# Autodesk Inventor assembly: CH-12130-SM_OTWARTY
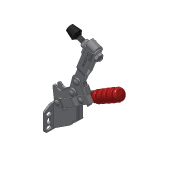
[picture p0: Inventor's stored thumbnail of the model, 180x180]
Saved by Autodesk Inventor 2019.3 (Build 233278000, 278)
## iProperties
Company: Î¢ÈíÖÐ¹ú
Created: 2012-09
Part Number: CH-12130-SM_OTWARTY
Material: Ogólny
Description: STEP AP203
Document SubType Name: Assembly
Designer: CADENGINEERING4
Sending System: SolidWorks 2010
Preprocessor: SwSTEP 2.0
Title: CH-12130-SM.STEP
Author: Î¢ÈíÓÃ»§
Revision Number: ÈÎºÎ
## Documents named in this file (12)
- D:\Vault_2016\Projekty\NASZ KATALOG\CLAMPTEK\STRONA\Vertical toggle clamp\CH-12130-SM\CH-12130-SM_OTWARTY.iam
- D:\Vault_2016\Projekty\NASZ KATALOG\CLAMPTEK\STEP FILES\Vertical toggle clamp\CH-12130-SM\CH-12130-04 CONNECTING-PLATE.ipt
- D:\Vault_2016\Projekty\NASZ KATALOG\CLAMPTEK\STEP FILES\Vertical toggle clamp\CH-12130-SM\CH-12130-SM-01 SIDE MOUNTED.ipt
- D:\Vault_2016\Projekty\NASZ KATALOG\CLAMPTEK\STEP FILES\Vertical toggle clamp\CH-12130-SM\CH-12130-08.ipt
- D:\Vault_2016\Projekty\NASZ KATALOG\CLAMPTEK\STEP FILES\Vertical toggle clamp\CH-12130-SM\CH-FW-516.ipt
- D:\Vault_2016\Projekty\NASZ KATALOG\CLAMPTEK\STEP FILES\Vertical toggle clamp\CH-12130-SM\CH-FC-56212 Nut.ipt
- D:\Vault_2016\Projekty\NASZ KATALOG\CLAMPTEK\STEP FILES\Vertical toggle clamp\CH-12130-SM\CH-12130-03 STRAIGHT HANDLE.ipt
- D:\Vault_2016\Projekty\NASZ KATALOG\CLAMPTEK\STEP FILES\Vertical toggle clamp\CH-12130-SM\CH-12130-05.ipt
- D:\Vault_2016\Projekty\NASZ KATALOG\CLAMPTEK\STEP FILES\Vertical toggle clamp\CH-12130-SM\CH-12130-07.ipt
- D:\Vault_2016\Projekty\NASZ KATALOG\CLAMPTEK\STEP FILES\Vertical toggle clamp\CH-12130-SM\CH-FC-56212 SPINDLE SUPPLIED.ipt
- D:\Vault_2016\Projekty\NASZ KATALOG\CLAMPTEK\STEP FILES\Vertical toggle clamp\CH-12130-SM\CH-12130-06.ipt
- D:\Vault_2016\Projekty\NASZ KATALOG\CLAMPTEK\STEP FILES\Vertical toggle clamp\CH-12130-SM\CH-12130-SM-02 U-BAR.ipt
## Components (15 placed, 11 different names)
1. CH-12130-SM-01 SIDE MOUNTED_2
2. CH-12130-04 CONNECTING-PLATE:2 — Zestawiające:5, Zestawiające:7, Zestawiające:8, Zestawiające:10, Zestawiające:11, Zestawiające:12, Zestawiające:13, Zestawiające:18
3. CH-12130-08:3 — Zestawiające:9, Zestawiające:10, Zestawiające:11, Zestawiające:31
4. CH-FW-516:3 — Zestawiające:20, Zestawiające:24, Zestawiające:27, Równoległe:2
5. CH-FC-56212 Nut:3 — Zestawiające:19, Zestawiające:20, Zestawiające:21, Zestawiające:27
6. CH-12130-03 STRAIGHT HANDLE:2 — Zestawiające:2, Zestawiające:3, Zestawiające:4, Zestawiające:9, Zestawiające:13, Zestawiające:14, Zestawiające:15, Zestawiające:16, Zestawiające:31
7. CH-FC-56212 Nut:4 — Zestawiające:21, Zestawiające:22, Zestawiające:25, Zestawiające:26, Zestawiające:28
8. CH-12130-05:2 — Zestawiające:1
9. CH-12130-08:4 — Zestawiające:1, Zestawiające:2, Zestawiające:3, Zestawiające:4
10. CH-12130-07:2 — Zestawiające:14, Zestawiające:15, Zestawiające:16
11. CH-FC-56212 SPINDLE SUPPLIED:2 — Zestawiające:19, Równoległe:1
12. CH-12130-06:3 — Zestawiające:17, Zestawiające:18
13. CH-12130-06:4 — Zestawiające:5, Zestawiające:6, Zestawiające:7, Zestawiające:8
14. CH-12130-SM-02 U-BAR:2 — Zestawiające:6, Zestawiające:12, Zestawiające:17, Zestawiające:23, Zestawiające:24, Równoległe:1, Zestawiające:25, Zestawiające:28, Kątowe:1
15. CH-FW-516:4 — Zestawiające:22, Zestawiające:23, Zestawiające:26, Równoległe:2, Kątowe:1
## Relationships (32: Mate 29, Flush 2, Angle 1)
- Zestawiające:1 [Mate]: CH-12130-05:2 ↔ CH-12130-08:4
- Zestawiające:2 [Mate]: CH-12130-03 STRAIGHT HANDLE:2 ↔ CH-12130-08:4
- Zestawiające:3 [Mate]: CH-12130-03 STRAIGHT HANDLE:2 ↔ CH-12130-08:4
- Zestawiające:4 [Mate]: CH-12130-03 STRAIGHT HANDLE:2 ↔ CH-12130-08:4
- Zestawiające:5 [Mate]: CH-12130-04 CONNECTING-PLATE:2 ↔ CH-12130-06:4
- Zestawiające:6 [Mate]: CH-12130-06:4 ↔ CH-12130-SM-02 U-BAR:2
- Zestawiające:7 [Mate]: CH-12130-04 CONNECTING-PLATE:2 ↔ CH-12130-06:4
- Zestawiające:8 [Mate]: CH-12130-04 CONNECTING-PLATE:2 ↔ CH-12130-06:4
- Zestawiające:9 [Mate]: CH-12130-08:3 ↔ CH-12130-03 STRAIGHT HANDLE:2
- Zestawiające:10 [Mate]: CH-12130-04 CONNECTING-PLATE:2 ↔ CH-12130-08:3
- Zestawiające:11 [Mate]: CH-12130-04 CONNECTING-PLATE:2 ↔ CH-12130-08:3
- Zestawiające:12 [Mate]: CH-12130-04 CONNECTING-PLATE:2 ↔ CH-12130-SM-02 U-BAR:2
- Zestawiające:13 [Mate]: CH-12130-04 CONNECTING-PLATE:2 ↔ CH-12130-03 STRAIGHT HANDLE:2
- Zestawiające:14 [Mate]: CH-12130-03 STRAIGHT HANDLE:2 ↔ CH-12130-07:2
- Zestawiające:15 [Mate]: CH-12130-03 STRAIGHT HANDLE:2 ↔ CH-12130-07:2
- Zestawiające:16 [Mate]: CH-12130-03 STRAIGHT HANDLE:2 ↔ CH-12130-07:2
- Zestawiające:17 [Mate]: CH-12130-06:3 ↔ CH-12130-SM-02 U-BAR:2
- Zestawiające:18 [Mate]: CH-12130-04 CONNECTING-PLATE:2 ↔ CH-12130-06:3
- Zestawiające:19 [Mate]: CH-FC-56212 Nut:3 ↔ CH-FC-56212 SPINDLE SUPPLIED:2
- Zestawiające:20 [Mate]: CH-FW-516:3 ↔ CH-FC-56212 Nut:3
- Zestawiające:21 [Mate]: CH-FC-56212 Nut:3 ↔ CH-FC-56212 Nut:4
- Zestawiające:22 [Mate]: CH-FC-56212 Nut:4 ↔ CH-FW-516:4
- Zestawiające:23 [Mate]: CH-12130-SM-02 U-BAR:2 ↔ CH-FW-516:4
- Zestawiające:24 [Mate]: CH-FW-516:3 ↔ CH-12130-SM-02 U-BAR:2
- Równoległe:1 [Flush]: CH-FC-56212 SPINDLE SUPPLIED:2 ↔ CH-12130-SM-02 U-BAR:2
- Zestawiające:25 [Mate]: CH-FC-56212 Nut:4 ↔ CH-12130-SM-02 U-BAR:2
- Zestawiające:26 [Mate]: CH-FC-56212 Nut:4 ↔ CH-FW-516:4
- Zestawiające:27 [Mate]: CH-FW-516:3 ↔ CH-FC-56212 Nut:3
- Zestawiające:28 [Mate]: CH-FC-56212 Nut:4 ↔ CH-12130-SM-02 U-BAR:2
- Równoległe:2 [Flush]: CH-FW-516:3 ↔ CH-FW-516:4
- Kątowe:1 [Angle]: CH-12130-SM-02 U-BAR:2 ↔ CH-FW-516:4
- Zestawiające:31 [Mate]: CH-12130-08:3 ↔ CH-12130-03 STRAIGHT HANDLE:2
